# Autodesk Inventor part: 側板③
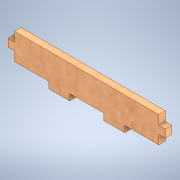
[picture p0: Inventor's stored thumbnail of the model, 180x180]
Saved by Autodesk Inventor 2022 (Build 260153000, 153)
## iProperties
Created: 2024-11
Part Number: 側板③
Material: MDF 中密度繊維ボード
Document SubType Name: Modeling
Designer: shimizu
Density: 0.8 g/cm^3
Appearance: サクラ材 - ナチュラル 抑えた光沢
Author: shimizu
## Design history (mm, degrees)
sketch "スケッチ1"
  geometry: L1 (-25.358, 1.343)-(29.642, 1.343); L2 (-4.358, -8.657)-(-4.358, -11.157); L3 (-4.358, -11.157)-(-12.358, -11.157); L4 (-12.358, -11.157)-(-12.358, -8.657); L5 (16.642, -8.657)-(16.642, -11.157); L6 (16.642, -11.157)-(8.642, -11.157); L7 (8.642, -11.157)-(8.642, -8.657); L8 (-25.358, -2.157)-(-27.858, -2.157); L9 (-27.858, -2.157)-(-27.858, -5.157); L10 (-27.858, -5.157)-(-25.358, -5.157); L11 (29.642, -2.157)-(32.142, -2.157); L12 (32.142, -2.157)-(32.142, -5.157); L13 (32.142, -5.157)-(29.642, -5.157); L14 (-25.358, -8.657)-(-25.358, -5.157); L15 (-25.358, -2.157)-(-25.358, 1.343); L16 (29.642, 1.343)-(29.642, -2.157); L17 (29.642, -5.157)-(29.642, -8.657); L18 (29.642, -8.657)-(16.642, -8.657); L19 (8.642, -8.657)-(-4.358, -8.657); L20 (-12.358, -8.657)-(-25.358, -8.657); 1 further point
  constraints: 40 end point, 11 parallel, 4 perpendicular, 3 horizontal
  dimensions: "d16" = 13 distance of L17.end L5.start; "d17" = 13 distance of L4.end L14.start; "d18" = 8 distance of L5.end L6.end; "d19" = 8 distance of L2.end L3.end; "d20" = 13 distance of L7.end L2.start; "d21" = 55 distance between parallel lines of L16 L15; "d22" = 60 distance between parallel lines of L12 L9
extrude "押し出し1" new body sketch "スケッチ1" distance "d14" = 2.5; taper "d15" = 0 deg
node "ソリッド1"
